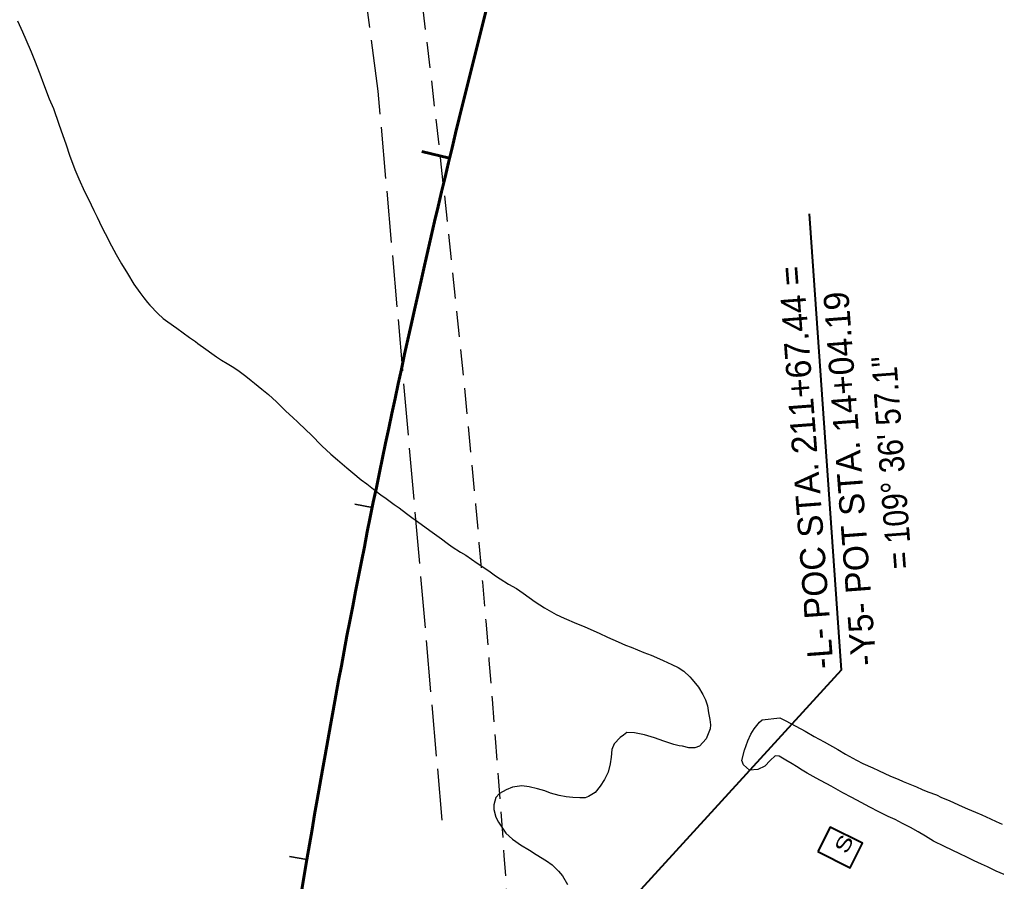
# Model space of a CAD drawing. Extents: x 2399800 to 2400616, y 567347 to 568869.
# Drawn here: x 2400111.3 to 2400384.1, y 568507.5 to 568748.4 of the extents above; entities that cross this region are included whole.
import ezdxf
from ezdxf.enums import TextEntityAlignment as Align

# ---------------------------------------------------------------- set-up
doc = ezdxf.new("R2010")
doc.units = 0
doc.header["$LTSCALE"] = 2.4
doc.linetypes.add('LONG_DASHED', pattern=[7.5, 6, -1.5])
doc.linetypes.add('MEDIUM_DASHED', pattern=[4.5, 3, -1.5])
for name, color, linetype, lineweight in [('11', 7, 'Continuous', 25), ('17', 7, 'MEDIUM_DASHED', 25), ('19', 7, 'LONG_DASHED', 25), ('3', 7, 'MEDIUM_DASHED', 35), ('38', 7, 'Continuous', 13), ('4', 7, 'Continuous', 35), ('61', 7, 'Continuous', 40), ('62', 7, 'Continuous', 60), ('8', 7, 'Continuous', 40)]:
    doc.layers.add(name, color=color, linetype=linetype, lineweight=lineweight)
doc.layers.add('28', color=7, linetype='Continuous')

msp = doc.modelspace()

# ---------------------------------------------------------------- linework, layer by layer
at = {"layer": '11'}
for points in [[(2400110.722, 568748.027), (2400112.146, 568744.947), (2400113.078, 568742.769), (2400114.538, 568739.38), (2400115.441, 568736.978), (2400117.001, 568733.194), (2400118.005, 568730.398), (2400119.59, 568726.231), (2400120.754, 568723.49), (2400122.31, 568719.099), (2400122.797, 568717.588), (2400124.299, 568713.356), (2400125.293, 568710.485), (2400126.749, 568706.488), (2400127.857, 568703.906), (2400129.446, 568700.348), (2400130.529, 568698.15), (2400132.027, 568695.061), (2400132.999, 568693.182), (2400134.303, 568690.346), (2400135.209, 568688.552), (2400136.968, 568685.124)], [(2400136.968, 568685.124), (2400138.33, 568682.738), (2400139.813, 568680.107), (2400141.435, 568677.382), (2400143.178, 568674.413), (2400144.859, 568672.137), (2400146.03, 568670.613), (2400147.08, 568669.333), (2400147.666, 568668.571), (2400149.946, 568666.217), (2400151.445, 568664.878), (2400152.695, 568663.953), (2400155.268, 568662.093), (2400157.002, 568660.8), (2400158.736, 568659.507), (2400160.414, 568658.373), (2400161.104, 568657.826), (2400163.342, 568656.314), (2400165.011, 568655.106), (2400166.325, 568654.096), (2400167.724, 568653.152), (2400169.283, 568652.262), (2400171.111, 568651.109), (2400172.66, 568650.144), (2400174.459, 568648.767), (2400175.968, 568647.503), (2400176.938, 568646.767), (2400178.997, 568645.05), (2400180.786, 568643.598), (2400183.03, 568641.552), (2400184.585, 568640.054), (2400185.655, 568638.924), (2400187.63, 568637.143), (2400189.064, 568635.889), (2400191.299, 568633.769), (2400192.704, 568632.29), (2400195.729, 568629.229), (2400198.243, 568626.92), (2400200.088, 568625.308), (2400202.697, 568623.139), (2400204.336, 568621.706), (2400206.75, 568619.79), (2400208.269, 568618.601), (2400210.618, 568616.771), (2400212.212, 568615.572), (2400213.676, 568614.543), (2400215.894, 568612.882), (2400217.294, 568611.937), (2400219.372, 568610.37), (2400220.826, 568609.266), (2400222.43, 568608.142), (2400224.854, 568606.302), (2400226.523, 568605.093), (2400229.096, 568603.233), (2400230.69, 568602.035), (2400232.154, 568601.005), (2400234.402, 568599.569), (2400235.961, 568598.679), (2400239.103, 568596.516), (2400242.321, 568594.343), (2400244.195, 568592.956), (2400245.528, 568592.096), (2400247.851, 568590.649), (2400250.119, 568589.362), (2400251.938, 568588.134), (2400255.34, 568585.632), (2400257.868, 568584.007), (2400261.125, 568582.133), (2400263.347, 568581.081), (2400266.813, 568579.637), (2400268.98, 568578.744), (2400271.716, 568577.547), (2400273.154, 568576.902), (2400275.526, 568575.83), (2400278.478, 568574.53), (2400280.485, 568573.581), (2400282.083, 568572.991), (2400285.623, 568571.537), (2400287.725, 568570.729), (2400289.173, 568570.159), (2400291.041, 568569.305), (2400293.478, 568568.148), (2400295.195, 568567.314), (2400296.819, 568566.34), (2400298.513, 568564.747), (2400299.174, 568563.975), (2400300.875, 568561.849), (2400302.127, 568559.781), (2400302.838, 568558.242), (2400303.381, 568556.571), (2400303.744, 568554.697), (2400304.033, 568552.831), (2400304.286, 568551.276), (2400304.148, 568550.228), (2400303.092, 568547.397), (2400301.226, 568545.357), (2400299.865, 568544.851), (2400298.199, 568544.917), (2400296.422, 568545.302), (2400295.524, 568545.419), (2400294.046, 568545.765)], [(2400337.977, 568534.145), (2400336.698, 568534.846), (2400334.775, 568535.859), (2400332.927, 568536.863), (2400331.294, 568537.762), (2400329.811, 568538.642), (2400328.272, 568539.681), (2400327.068, 568540.372), (2400325.305, 568541.44), (2400323.476, 568542.593), (2400322.269, 568542.676), (2400320.875, 568541.336), (2400319.452, 568539.771), (2400317.498, 568538.809), (2400315.194, 568538.654), (2400313.479, 568540.097), (2400313.028, 568541.298), (2400313.72, 568544.253), (2400314.672, 568546.869), (2400315.516, 568548.662), (2400316.48, 568550.211), (2400317.942, 568552.074), (2400318.64, 568552.745), (2400323.577, 568553.24)], [(2400323.577, 568553.24), (2400325.08, 568552.51), (2400328.067, 568550.9), (2400330.699, 568549.489), (2400333.246, 568548.013), (2400335.953, 568546.593), (2400339.78, 568544.416), (2400341.973, 568543.139), (2400345.024, 568541.444), (2400346.808, 568540.525), (2400349.544, 568539.329), (2400351.197, 568538.58), (2400354.567, 568536.996), (2400356.66, 568536.113), (2400358.098, 568535.468), (2400360.34, 568534.564), (2400361.788, 568533.994), (2400363.366, 568533.255), (2400364.954, 568532.59), (2400367.355, 568531.742), (2400368.783, 568531.022), (2400370.95, 568530.128), (2400372.314, 568529.493), (2400374.546, 568528.515), (2400376.049, 568527.785), (2400378.291, 568526.883), (2400380.019, 568526.123), (2400382.465, 568525.041), (2400384.044, 568524.301), (2400385.697, 568523.552)], [(2400294.046, 568545.765), (2400291.206, 568546.747), (2400288.58, 568547.624), (2400285.804, 568548.52), (2400283.064, 568549.108), (2400280.864, 568549.168), (2400279.923, 568548.378), (2400279.001, 568547.737), (2400277.324, 568545.977), (2400276.734, 568544.38), (2400276.534, 568542.274), (2400276.214, 568540.412), (2400275.686, 568538.122), (2400274.652, 568536.049), (2400273.414, 568534.155), (2400272.037, 568532.356), (2400270.223, 568531.3), (2400269.256, 568530.894), (2400267.73, 568530.865), (2400265.839, 568530.961), (2400263.968, 568531.206), (2400262.032, 568531.536), (2400259.61, 568532.234), (2400258.013, 568532.824), (2400255.956, 568533.398), (2400253.6, 568534.012), (2400251.579, 568534.276), (2400248.936, 568533.861), (2400247.172, 568533.179), (2400245.358, 568532.122), (2400244.303, 568531.042), (2400243.719, 568528.911), (2400243.787, 568527.684), (2400244.336, 568525.48), (2400245.067, 568524.09), (2400247.099, 568521.007), (2400248.944, 568519.395), (2400249.923, 568518.733), (2400251.172, 568517.808), (2400253.71, 568516.257), (2400255.613, 568515.094), (2400258.496, 568513.27), (2400260.024, 568512.156), (2400261.849, 568510.394), (2400262.9, 568509.114), (2400264.327, 568506.643)], [(2400386.287, 568509.465), (2400384.055, 568510.443), (2400381.618, 568511.6), (2400379.89, 568512.359), (2400377.882, 568513.307), (2400375.885, 568514.331), (2400373.877, 568515.279), (2400371.72, 568516.247), (2400369.572, 568517.29), (2400366.576, 568518.824), (2400364.318, 568520.187), (2400362.275, 568521.444), (2400360.062, 568522.571), (2400357.85, 568523.699), (2400355.787, 568524.807), (2400353.845, 568525.67), (2400351.277, 568526.997), (2400348.711, 568528.323), (2400346.293, 568529.63), (2400343.726, 568530.956), (2400341.234, 568532.272), (2400339.255, 568533.445), (2400337.977, 568534.145)]]:
    msp.add_lwpolyline(points, dxfattribs=at)
at = {"layer": '17'}
msp.add_arc((2395446.846, 568174.368), 4811.888, 358.84472, 7.18511, dxfattribs=at)
at = {"layer": '19'}
msp.add_lwpolyline([(2400229.34, 568524.653), (2400211.491, 568728.334), (2400192.97, 568869.329)], dxfattribs=at)
at = {"layer": '3', "linetype": 'Continuous', "lineweight": 60}
msp.add_line((2400231.397, 568709.644), (2400223.617, 568711.506), dxfattribs=at)
at = {"layer": '38'}
msp.add_arc((2403051.703, 568034.46), 2900, 165.14066, 170.48811, dxfattribs=at)
at = {"layer": '4'}
for p, q in [((2400209.796, 568612.01), (2400204.896, 568613.005)), ((2400186.645, 568514.515), (2400191.574, 568513.689))]:
    msp.add_line(p, q, dxfattribs=at)
at = {"layer": '61'}
for p, q in [((2400331.812, 568694.105), (2400340.726, 568566.615)), ((2400340.726, 568566.615), (2400172.663, 568382.492))]:
    msp.add_line(p, q, dxfattribs=at)
at = {"layer": '62'}
for start, end in [(165.14066, 170.48811), (170.48821, 180.54867)]:
    msp.add_arc((2403051.703, 568034.46), 2900, start, end, dxfattribs=at)
at = {"layer": '8'}
msp.add_lwpolyline([(2400334.251, 568515.864), (2400343.233, 568511.343), (2400346.701, 568518.235), (2400337.719, 568522.755)], close=True, dxfattribs=at)

# ---------------------------------------------------------------- texts
at = {"layer": '28', "width": 1.35}
msp.add_text('S', height=4, rotation=62.433, dxfattribs=at).set_placement((2400343.313, 568517.095), align=Align.CENTER)
at = {"layer": '61'}
for s, p in [('-L- POC STA. 211+67.44 =', (2400338.618, 568567.15)), ('-Y5- POT STA. 14+04.19', (2400350.584, 568568.051))]:
    msp.add_text(s, height=7, rotation=94.303, dxfattribs=at).set_placement(p)
at = {"layer": '61', "width": 0.9}
msp.add_text('= 109° 36\' 57.1"', height=7, rotation=94.303, dxfattribs=at).set_placement((2400356.082, 568654.602), align=Align.RIGHT)

doc.saveas('drawing.dxf')
